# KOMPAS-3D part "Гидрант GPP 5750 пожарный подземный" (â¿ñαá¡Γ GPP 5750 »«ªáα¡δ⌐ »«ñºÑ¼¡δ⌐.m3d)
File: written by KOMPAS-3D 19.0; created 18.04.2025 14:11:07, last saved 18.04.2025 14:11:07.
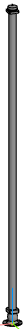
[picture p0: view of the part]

Document properties: Полное имя файла: E:\Dendor Работа Сачек\3D для проекитирвщиков\11.1 Тип GPP. Гидрант пожарный подземный\stp_Тип GPP. 750-6000 Гидрант пожарный подземный\Гидрант GPP 5750 пожарный подземный.m3d

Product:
- Part/product: Гидрант GPP 5750 пожарный подземный

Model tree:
1. Операция без истории:1  (labels: Гидрант GPP 5750 пожарный подземный)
